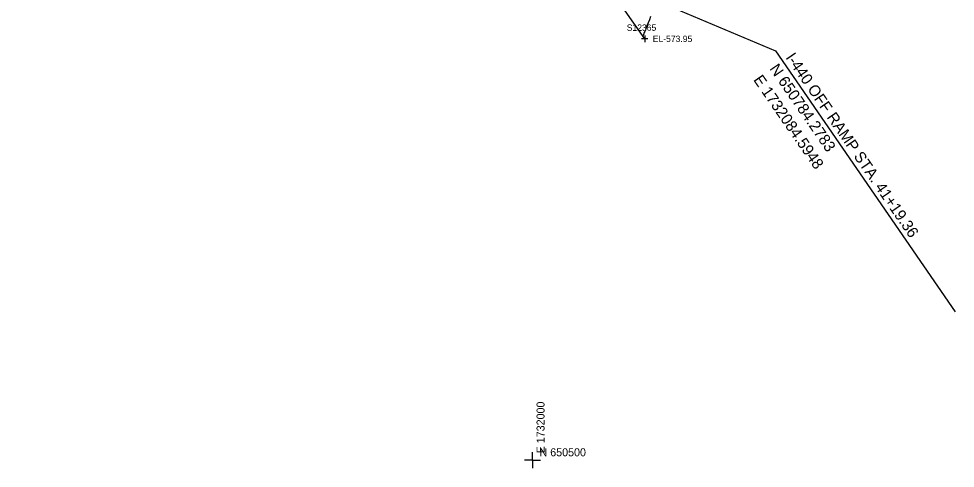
# Model space of a CAD drawing. Extents: x 1729869 to 1735532, y 648588 to 653771.
# Drawn here: x 1731679 to 1732264, y 650495 to 650776 of the extents above; entities that cross this region are included whole.
import ezdxf

# ---------------------------------------------------------------- set-up
doc = ezdxf.new("R2010")
doc.units = 0
for name, color, linetype in [('SURVEY - CENTERLINE - Preliminary Text', 7, 'Continuous'), ('SURVEY - CONTOURS - Intermediate with optional Text', 7, 'Continuous'), ('SURVEY - CONTROL - Grid', 7, 'Continuous'), ('SURVEY - CONTROL - Grid Text', 7, 'Continuous'), ('SURVEY - TRANSPORTATION - Roads', 7, 'Continuous'), ('SURVEY - TRANSPORTATION - Roads - Points - Elevations', 7, 'Continuous'), ('SURVEY - TRANSPORTATION - Roads - Points - Locators', 7, 'Continuous'), ('SURVEY - TRANSPORTATION - Roads - Points - Numbers', 7, 'Continuous')]:
    doc.layers.add(name, color=color, linetype=linetype)

msp = doc.modelspace()

# ---------------------------------------------------------------- linework, layer by layer
at = {"layer": 'SURVEY - CENTERLINE - Preliminary Text'}
for p, q in [((1732084.59, 650784.28), (1732151.69, 650756.04)), ((1732151.69, 650756.04), (1732264.03, 650592.88))]:
    msp.add_line(p, q, dxfattribs=at)
at = {"layer": 'SURVEY - CONTOURS - Intermediate with optional Text'}
msp.add_lwpolyline([(1732073.68, 650777.4), (1732072.95, 650775.39), (1732072.21, 650773.41), (1732071.48, 650771.51), (1732070.78, 650769.75), (1732070.45, 650768.92), (1732070.12, 650768.13), (1732069.81, 650767.37), (1732069.2, 650765.91), (1732068.9, 650765.2)], dxfattribs=at)
at = {"layer": 'SURVEY - CONTROL - Grid'}
for q in [(1732000, 650505), (1731995, 650500), (1732005, 650500), (1732000, 650495)]:
    msp.add_line((1732000, 650500), q, dxfattribs=at)
at = {"layer": 'SURVEY - TRANSPORTATION - Roads'}
msp.add_lwpolyline([(1732070.09, 650763.48), (1732042.68, 650802.88), (1732041.54, 650804.52), (1732023.43, 650830.89), (1731999.56, 650865.44), (1731970.03, 650908.23), (1731954.16, 650931.29), (1731943.93, 650946.1), (1731925.72, 650972.41), (1731901.87, 651006.98), (1731875.73, 651044.83), (1731857.56, 651071.17), (1731837.15, 651100.82), (1731829.22, 651112.36), (1731814.38, 651133.71), (1731800.81, 651153.5), (1731787.28, 651173.33), (1731777.06, 651188.14), (1731750.84, 651225.94), (1731731.61, 651253.98), (1731715.78, 651277.07), (1731695.36, 651306.73), (1731670.42, 651342.98)], dxfattribs=at)
at = {"layer": 'SURVEY - TRANSPORTATION - Roads - Points - Locators'}
for p, q in [((1732072.09, 650763.48), (1732068.09, 650763.48)), ((1732070.09, 650765.48), (1732070.09, 650761.48))]:
    msp.add_line(p, q, dxfattribs=at)

# ---------------------------------------------------------------- texts
at = {"layer": 'SURVEY - CENTERLINE - Preliminary Text'}
for s, p in [('I-440 OFF RAMP STA. 41+19.36', (1732157.82, 650751.76)), ('N 650784.2783', (1732147.73, 650744.81)), ('E 1732084.5948', (1732137.64, 650737.86))]:
    msp.add_text(s, height=7, rotation=304.54924, dxfattribs=at).set_placement(p)
at = {"layer": 'SURVEY - CONTROL - Grid Text'}
msp.add_text(' E 1732000 ', height=5, rotation=90, dxfattribs=at).set_placement((1732007.5, 650502.5))
msp.add_text(' N 650500 ', height=5, dxfattribs=at).set_placement((1732002.5, 650502.5))
at = {"layer": 'SURVEY - TRANSPORTATION - Roads - Points - Elevations'}
msp.add_text('EL-573.95', height=4, dxfattribs=at).set_placement((1732075.09, 650761.48))
at = {"layer": 'SURVEY - TRANSPORTATION - Roads - Points - Numbers'}
msp.add_text('S12365', height=4, dxfattribs=at).set_placement((1732058.85, 650768.48))

doc.saveas('drawing.dxf')
